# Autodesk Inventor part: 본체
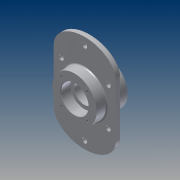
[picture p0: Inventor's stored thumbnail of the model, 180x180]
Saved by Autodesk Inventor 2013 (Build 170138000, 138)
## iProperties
Created: 2015-02
Part Number: 본체
Material: 알루미늄 6061
Document SubType Name: Modeling
Designer: cad8
Density: 2.40731 g/cm^3
Mass: 1476.46 g
Surface Area: 942.61 cm^2
Volume: 613.321 cm^3
Author: cad8
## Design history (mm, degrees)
sketch "스케치1"
  geometry: L1 (0, 35)-(50, 35); L2 (50, 35)-(50, -35); L3 (50, -35)-(0, -35); L4 (0, -35)-(0, 35); L5 (31, 35)-(31, 13); L6 (31, 13)-(22.5, 13); L7 (22.5, 13)-(22.5, -13); L8 (22.5, -13)-(31, -13); L9 (31, -13)-(31, -35); 2 further points
  constraints: 18 end point, 5 parallel, 3 perpendicular, 2 point on line, 1 coincident, 1 horizontal, 1 midpoint
  dimensions: "d0" = 70 distance of L3.end L1.start; "d2" = 100 diameter of L2 L4; "d3" = 22 distance of L5.start L5.end; "d4" = 22 distance of L8.end L9.end; "d5" = 62 diameter of L5 L4; "d6" = 62 diameter of L9 L4; "d7" = 45 diameter of L7 L4
revolve "회전1" sketch "스케치1" stored, may be unused: angle "d8" = 90 deg
node "작업 평면1"
sketch "스케치2"
  geometry: L1 (-70, 60)-(-70, -60); L2 (70, -60)-(70, 60); C1 r 50 at (0, 0) reference; 5 further points; 2 other entities
  constraints: 4 end point, 1 coincident, 1 horizontal alignment, 1 midpoint, 1 parallel, 1 vertical alignment, 8 other
  dimensions: "d10" = 140 distance of L2.end L1.start; "d12" = 120 distance of L1.start L1.end; "d15" = 70 distance from line of L1 point (0, 0); "d16" = 70 distance of point (0, 0) point (70, 0)
extrude "돌출1" join sketch "스케치2" distance "d17" = 12; taper "d18" = 0 deg
sketch "스케치3"
  geometry: L1 (70, -60)-(70, 60) reference; L2 (-70, 60)-(-70, -60) reference; L3 (53, 60)-(53, -60); L4 (-53, -60)-(-53, 60); C1 r 50 at (0, 0) reference; C2 r 10 at (0, 93); 2 further points; 2 other entities
  constraints: 4 end point, 3 parallel, 1 centre point, 1 horizontal alignment, 1 vertical alignment, 8 other
  dimensions: "d19" = 17 distance between parallel lines of L4 L2; "d20" = 20 diameter of C2
extrude "돌출2" join sketch "스케치3" distance "d21" = 5; taper "d22" = 0 deg
sketch "스케치4"
  geometry: C1 r 10 at (0, 0) reference; C2 r 5.5 at (0, 0); 1 further point
  constraints: 1 centre point, 1 coincident
  dimensions: "d23" = 11 diameter of C2
extrude "돌출3" cut sketch "스케치4" stored distance "d25" = 5; taper "d26" = 0 deg
node "작업 평면2"
sketch "스케치6" dims "d31" = 82
  geometry: L1 (0, 0)-(0, 50); L2 (0, 0)-(35.355, 35.355); A1 r 50 centre (0, 0) between (0, 50) and (35.355, 35.355) reference; 2 further points
  constraints: 4 end point, 2 point on circle, 1 coincident, 1 point on line, 1 vertical, 3 other
  dimensions: "d30" = 45 deg angle of L2 L1
hole "구멍1" sketch "스케치6" at (28.991, 28.991) diameter "d33" = 4.917; stored, may be unused: countersink angle "d37" = 90 deg, drill point angle "d39" = 118 deg; dims "d34" = 10, "d35" = 4, "d36" = 2, "d38" = 13
fillet "모깎기1" dims "d43" = 0.3
chamfer "모따기1" distance "d44" = 1; stored, may be unused: second distance "d45" = 2, angle "d46" = 45 deg
node "작업 평면3"
sketch "스케치7"
  geometry: 2 further points
  constraints: 1 vertical alignment, 1 other
  dimensions: "d48" = 65 distance of point (0, -65) point (0, 0)
feature "엠보싱1" sketch "스케치7" dims "d0" = 70, "d2" = 100, "d3" = 22, "d4" = 22, "d5" = 62, "d6" = 62, "d7" = 45, "d49" = 1, "d50" = 0
fillet "모깎기2" dims "d51" = 3
node "솔리드1"
pattern_linear "직사각형 패턴1"
pattern_circular "원형 패턴1" dims angle "d41" = 360 deg
mirror "대칭1"
sketch "스케치5"
  geometry: L1 (70, -60)-(70, 60) reference; L2 (-70, 60)-(-70, -60) reference; L3 (53, 60)-(53, -60); L4 (-53, -60)-(-53, 60); C1 r 10 at (0, 93) reference; 2 further points; 2 other entities
  constraints: 4 end point, 3 parallel, 2 horizontal alignment, 6 other
  dimensions: "d27" = 17 distance between parallel lines of L4 L2
other parameters: "d9" = -23
